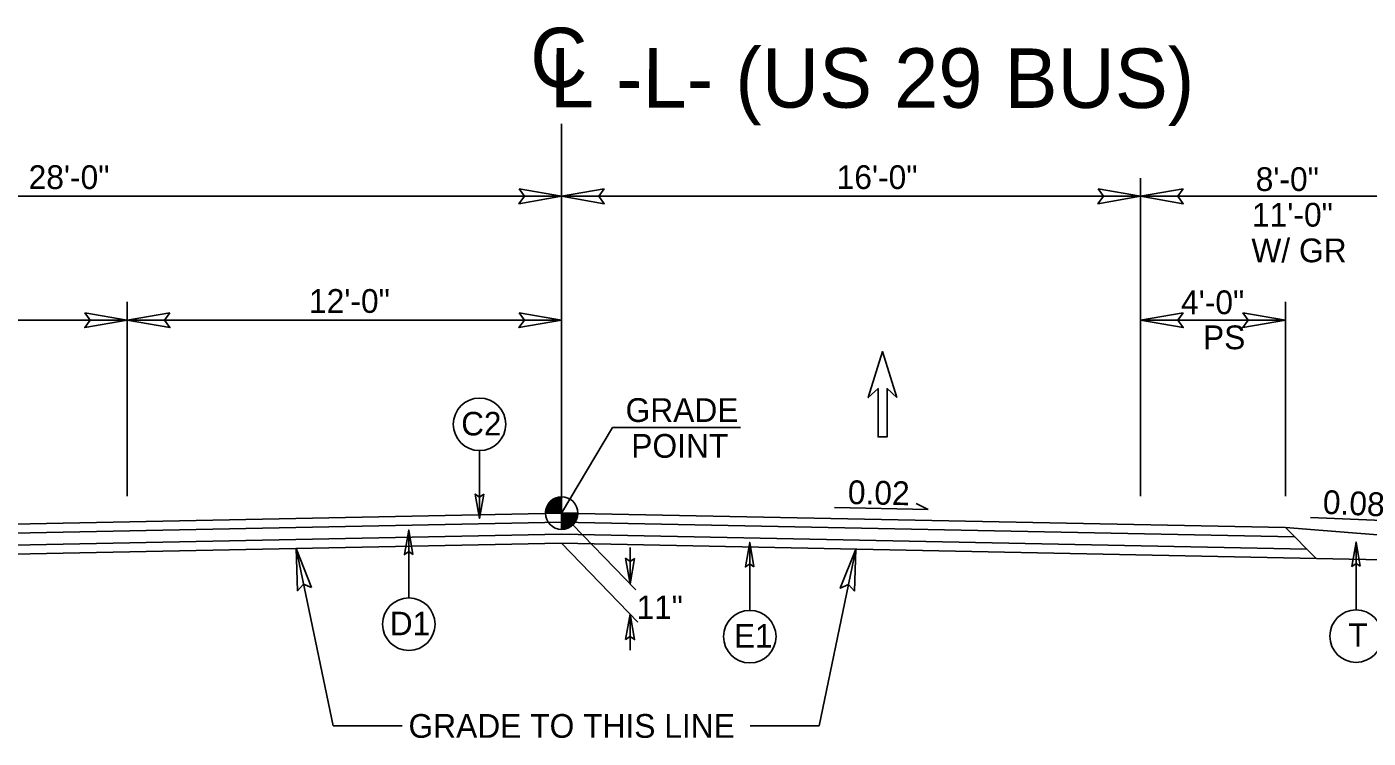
# Model space of a CAD drawing. Extents: x 1901582 to 1902252, y 193723 to 194156.
# Drawn here: x 1902073.81 to 1902110.87, y 194106.96 to 194126.6 of the extents above; entities that cross this region are included whole.
import ezdxf

# ---------------------------------------------------------------- set-up
doc = ezdxf.new("R2010")
doc.units = 0
for name, color, linetype in [('Old_Level_1', 7, 'Continuous'), ('Old_Level_11', 7, 'Continuous'), ('Old_Level_2', 7, 'Continuous'), ('Old_Level_20', 7, 'Continuous'), ('Prop Dimension', 7, 'Continuous'), ('Prop Dimension Text', 7, 'Continuous'), ('Typical Grade Point Symbol CELL', 7, 'Continuous'), ('Typical Pavement Slope Information CELL', 7, 'Continuous'), ('Typical Terminator CELL', 7, 'Continuous'), ('Typical Text Centerline CELL', 7, 'Continuous'), ('Typical Text Grade Point CELL', 7, 'Continuous')]:
    doc.layers.add(name, color=color, linetype=linetype)

# ---------------------------------------------------------------- blocks, each defined once
blk = doc.blocks.new('TERMINATOR')
at = {"layer": 'Typical Terminator CELL'}
blk.add_lwpolyline([(-0.469, 0.081), (0, 0), (-0.471, -0.083), (-0.411, 0)], close=True, dxfattribs=at)

msp = doc.modelspace()

# ---------------------------------------------------------------- linework, layer by layer
at = {"layer": 'Old_Level_1'}
for p, q in [((1902104.586, 194113.636), (1902104.586, 194122.419)), ((1902088.586, 194121.919), (1902060.586, 194121.919)), ((1902104.586, 194121.919), (1902088.586, 194121.919)), ((1902112.586, 194121.919), (1902104.586, 194121.919)), ((1902076.586, 194113.636), (1902076.586, 194119)), ((1902108.586, 194113.636), (1902108.586, 194119)), ((1902076.586, 194118.5), (1902060.586, 194118.5)), ((1902088.586, 194118.5), (1902076.586, 194118.5)), ((1902108.586, 194118.5), (1902104.586, 194118.5)), ((1902088.586, 194113.169), (1902060.586, 194112.609)), ((1902088.586, 194113.169), (1902090.635, 194111.053)), ((1902088.586, 194113.169), (1902108.586, 194112.769)), ((1902088.586, 194112.919), (1902060.586, 194112.359)), ((1902088.586, 194112.919), (1902108.842, 194112.514)), ((1902108.586, 194112.769), (1902109.437, 194111.919)), ((1902108.586, 194112.769), (1902112.586, 194112.449)), ((1902088.586, 194112.336), (1902057.344, 194111.711)), ((1902088.586, 194112.586), (1902057.599, 194111.966)), ((1902088.586, 194112.586), (1902109.182, 194112.174)), ((1902088.586, 194112.336), (1902090.693, 194110.16)), ((1902088.586, 194112.336), (1902115.167, 194111.804)), ((1902081.248, 194112.189), (1902082.271, 194107.298)), ((1902090.477, 194112.216), (1902090.477, 194111.216)), ((1902096.721, 194112.173), (1902095.702, 194107.298)), ((1902090.477, 194110.382), (1902090.477, 194109.382)), ((1902082.271, 194107.298), (1902084.181, 194107.298)), ((1902093.793, 194107.298), (1902095.702, 194107.298))]:
    msp.add_line(p, q, dxfattribs=at)
at = {"layer": 'Old_Level_11'}
for p, q in [((1902088.586, 194113.169), (1902088.586, 194123.919)), ((1902086.319, 194114.895), (1902086.319, 194113.021)), ((1902084.364, 194110.826), (1902084.364, 194112.7)), ((1902093.787, 194110.484), (1902093.787, 194112.358)), ((1902110.54, 194110.497), (1902110.54, 194112.371))]:
    msp.add_line(p, q, dxfattribs=at)
for points in [[(1902086.435, 194113.693), (1902086.319, 194113.021), (1902086.2, 194113.696), (1902086.319, 194113.611)], [(1902084.479, 194112.029), (1902084.364, 194112.7), (1902084.244, 194112.025), (1902084.364, 194112.111)], [(1902093.902, 194111.687), (1902093.787, 194112.358), (1902093.667, 194111.683), (1902093.787, 194111.769)], [(1902110.655, 194111.7), (1902110.54, 194112.371), (1902110.42, 194111.696), (1902110.54, 194111.782)]]:
    msp.add_lwpolyline(points, close=True, dxfattribs=at)
for centre in [(1902086.319, 194115.621), (1902084.364, 194110.101), (1902093.787, 194109.759), (1902110.54, 194109.772)]:
    msp.add_circle(centre, 0.725, dxfattribs=at)
at = {"layer": 'Prop Dimension'}
msp.add_lwpolyline([(1902097.852, 194116.357), (1902097.581, 194116.607), (1902097.581, 194115.274), (1902097.331, 194115.274), (1902097.331, 194116.607), (1902097.06, 194116.357), (1902097.456, 194117.628)], close=True, dxfattribs=at)
msp.add_lwpolyline([(1902097.852, 194116.357), (1902097.581, 194116.607), (1902097.581, 194115.274), (1902097.331, 194115.274), (1902097.331, 194116.607), (1902097.06, 194116.357), (1902097.456, 194117.628)], close=True, dxfattribs=at)
at = {"layer": 'Typical Grade Point Symbol CELL'}
for p, q in [((1902088.586, 194113.169), (1902088.586, 194113.617)), ((1902088.139, 194113.169), (1902088.586, 194113.169)), ((1902088.587, 194112.722), (1902088.586, 194113.169)), ((1902089.034, 194113.169), (1902088.586, 194113.169)), ((1902088.586, 194113.169), (1902088.587, 194112.722))]:
    msp.add_line(p, q, dxfattribs=at)
for points in [[(1902088.171, 194113.334), (1902088.171, 194113.169)], [(1902088.18, 194113.355), (1902088.18, 194113.169)], [(1902088.189, 194113.374), (1902088.189, 194113.169)], [(1902088.197, 194113.39), (1902088.197, 194113.169)], [(1902088.206, 194113.405), (1902088.206, 194113.169)], [(1902088.215, 194113.419), (1902088.215, 194113.169)], [(1902088.224, 194113.432), (1902088.224, 194113.169)], [(1902088.233, 194113.444), (1902088.233, 194113.169)], [(1902088.242, 194113.455), (1902088.242, 194113.169)], [(1902088.251, 194113.466), (1902088.251, 194113.169)], [(1902088.26, 194113.475), (1902088.26, 194113.169)], [(1902088.269, 194113.484), (1902088.269, 194113.169)], [(1902088.278, 194113.493), (1902088.278, 194113.169)], [(1902088.287, 194113.501), (1902088.287, 194113.169)], [(1902088.296, 194113.509), (1902088.296, 194113.169)], [(1902088.305, 194113.517), (1902088.305, 194113.169)], [(1902088.314, 194113.524), (1902088.314, 194113.169)], [(1902088.323, 194113.53), (1902088.323, 194113.169)], [(1902088.332, 194113.537), (1902088.332, 194113.169)], [(1902088.341, 194113.543), (1902088.341, 194113.169)], [(1902088.35, 194113.549), (1902088.35, 194113.169)], [(1902088.359, 194113.554), (1902088.359, 194113.169)], [(1902088.368, 194113.559), (1902088.368, 194113.169)], [(1902088.377, 194113.564), (1902088.377, 194113.169)], [(1902088.385, 194113.569), (1902088.385, 194113.169)], [(1902088.394, 194113.573), (1902088.394, 194113.169)], [(1902088.403, 194113.577), (1902088.403, 194113.169)], [(1902088.412, 194113.581), (1902088.412, 194113.169)], [(1902088.421, 194113.585), (1902088.421, 194113.169)], [(1902088.43, 194113.589), (1902088.43, 194113.169)], [(1902088.439, 194113.592), (1902088.439, 194113.169)], [(1902088.448, 194113.595), (1902088.448, 194113.169)], [(1902088.457, 194113.598), (1902088.457, 194113.169)], [(1902088.466, 194113.6), (1902088.466, 194113.169)], [(1902088.475, 194113.603), (1902088.475, 194113.169)], [(1902088.484, 194113.605), (1902088.484, 194113.169)], [(1902088.493, 194113.607), (1902088.493, 194113.169)], [(1902088.502, 194113.609), (1902088.502, 194113.169)], [(1902088.511, 194113.611), (1902088.511, 194113.169)], [(1902088.52, 194113.612), (1902088.52, 194113.169)], [(1902088.529, 194113.613), (1902088.529, 194113.169)], [(1902088.538, 194113.614), (1902088.538, 194113.169)], [(1902088.547, 194113.615), (1902088.547, 194113.169)], [(1902088.556, 194113.616), (1902088.556, 194113.169)], [(1902088.564, 194113.616), (1902088.564, 194113.169)], [(1902088.573, 194113.617), (1902088.573, 194113.169)], [(1902088.582, 194113.617), (1902088.582, 194113.617), (1902088.582, 194113.169)], [(1902088.144, 194113.233), (1902088.144, 194113.169)], [(1902088.153, 194113.279), (1902088.153, 194113.169)], [(1902088.162, 194113.309), (1902088.162, 194113.169)], [(1902088.593, 194113.169), (1902088.593, 194112.722), (1902088.593, 194112.722)], [(1902088.602, 194113.169), (1902088.602, 194112.722)], [(1902088.611, 194113.169), (1902088.611, 194112.723)], [(1902088.62, 194113.169), (1902088.62, 194112.723)], [(1902088.629, 194113.169), (1902088.629, 194112.724)], [(1902088.638, 194113.169), (1902088.638, 194112.725)], [(1902088.647, 194113.169), (1902088.647, 194112.726)], [(1902088.656, 194113.169), (1902088.656, 194112.728)], [(1902088.665, 194113.169), (1902088.665, 194112.728)], [(1902088.674, 194113.169), (1902088.674, 194112.73)], [(1902088.683, 194113.169), (1902088.683, 194112.732)], [(1902088.692, 194113.169), (1902088.692, 194112.734)], [(1902088.701, 194113.169), (1902088.701, 194112.736)], [(1902088.71, 194113.169), (1902088.71, 194112.739)], [(1902088.719, 194113.169), (1902088.719, 194112.741)], [(1902088.728, 194113.169), (1902088.728, 194112.744)], [(1902088.737, 194113.169), (1902088.737, 194112.747)], [(1902088.746, 194113.169), (1902088.746, 194112.75)], [(1902088.754, 194113.169), (1902088.754, 194112.754)], [(1902088.763, 194113.169), (1902088.763, 194112.758)], [(1902088.772, 194113.169), (1902088.772, 194112.762)], [(1902088.781, 194113.169), (1902088.781, 194112.766)], [(1902088.79, 194113.169), (1902088.79, 194112.77)], [(1902088.799, 194113.169), (1902088.799, 194112.775)], [(1902088.808, 194113.169), (1902088.808, 194112.78)], [(1902088.817, 194113.169), (1902088.817, 194112.785)], [(1902088.826, 194113.169), (1902088.826, 194112.791)], [(1902088.835, 194113.169), (1902088.835, 194112.797)], [(1902088.844, 194113.169), (1902088.844, 194112.803)], [(1902088.853, 194113.169), (1902088.853, 194112.809)], [(1902088.862, 194113.169), (1902088.862, 194112.816)], [(1902088.871, 194113.169), (1902088.871, 194112.823)], [(1902088.88, 194113.169), (1902088.88, 194112.831)], [(1902088.889, 194113.169), (1902088.889, 194112.839)], [(1902088.898, 194113.169), (1902088.898, 194112.847)], [(1902088.907, 194113.169), (1902088.907, 194112.856)], [(1902088.916, 194113.169), (1902088.916, 194112.866)], [(1902088.925, 194113.169), (1902088.925, 194112.876)], [(1902088.934, 194113.169), (1902088.934, 194112.887)], [(1902088.942, 194113.169), (1902088.942, 194112.898)], [(1902088.951, 194113.169), (1902088.951, 194112.91)], [(1902088.96, 194113.169), (1902088.96, 194112.922)], [(1902088.969, 194113.169), (1902088.969, 194112.936)], [(1902088.978, 194113.169), (1902088.978, 194112.952)], [(1902088.987, 194113.169), (1902088.987, 194112.969)], [(1902088.996, 194113.169), (1902088.996, 194112.988)], [(1902089.005, 194113.169), (1902089.005, 194113.009)], [(1902089.014, 194113.169), (1902089.014, 194113.036)], [(1902089.023, 194113.169), (1902089.023, 194113.068)], [(1902089.032, 194113.169), (1902089.032, 194113.12)]]:
    msp.add_lwpolyline(points, dxfattribs=at)
msp.add_circle((1902088.587, 194113.169), 0.448, dxfattribs=at)
for start, end in [(90.0095, 180.0095), (270.0095, 0.0095)]:
    msp.add_arc((1902088.587, 194113.169), 0.448, start, end, dxfattribs=at)
at = {"layer": 'Typical Pavement Slope Information CELL'}
for p, q in [((1902098.716, 194113.27), (1902098.383, 194113.437)), ((1902096.129, 194113.324), (1902098.716, 194113.27)), ((1902109.281, 194113.05), (1902111.867, 194112.935))]:
    msp.add_line(p, q, dxfattribs=at)
at = {"layer": 'Typical Terminator CELL'}
for points in [[(1902087.415, 194122.121), (1902088.586, 194121.919), (1902087.408, 194121.711), (1902087.558, 194121.919)], [(1902089.758, 194122.121), (1902088.586, 194121.919), (1902089.765, 194121.711), (1902089.615, 194121.919)], [(1902103.415, 194122.121), (1902104.586, 194121.919), (1902103.408, 194121.711), (1902103.558, 194121.919)], [(1902105.758, 194122.121), (1902104.586, 194121.919), (1902105.765, 194121.711), (1902105.615, 194121.919)], [(1902075.415, 194118.702), (1902076.586, 194118.5), (1902075.408, 194118.292), (1902075.558, 194118.5)], [(1902077.758, 194118.702), (1902076.586, 194118.5), (1902077.765, 194118.292), (1902077.615, 194118.5)], [(1902087.415, 194118.702), (1902088.586, 194118.5), (1902087.408, 194118.292), (1902087.558, 194118.5)], [(1902105.758, 194118.702), (1902104.586, 194118.5), (1902105.765, 194118.292), (1902105.615, 194118.5)], [(1902107.415, 194118.702), (1902108.586, 194118.5), (1902107.408, 194118.292), (1902107.558, 194118.5)], [(1902081.674, 194111.113), (1902081.248, 194112.189), (1902081.285, 194111.026), (1902081.453, 194111.21)], [(1902096.68, 194111.017), (1902096.721, 194112.173), (1902096.288, 194111.093), (1902096.517, 194111.194)]]:
    msp.add_lwpolyline(points, close=True, dxfattribs=at)
at = {"layer": 'Typical Text Grade Point CELL'}
for p, q in [((1902088.586, 194113.169), (1902089.99, 194115.53)), ((1902089.99, 194115.53), (1902093.528, 194115.53))]:
    msp.add_line(p, q, dxfattribs=at)

# ---------------------------------------------------------------- block references
at = {"layer": 'Old_Level_1', "xscale": 1.5, "yscale": 1.5}
for p, rotation in [((1902090.477, 194111.216), -90), ((1902090.477, 194110.382), 90)]:
    msp.add_blockref('TERMINATOR', p, dxfattribs=dict(at, rotation=rotation))

# ---------------------------------------------------------------- texts
at = {"layer": 'Old_Level_1'}
for s, p in [('28\'-0"', (1902073.859, 194122.117)), ('16\'-0"', (1902096.187, 194122.117)), ('8\'-0"', (1902107.766, 194122.063)), ('11\'-0"', (1902107.664, 194121.079)), ('W/ GR', (1902107.647, 194120.095)), ('12\'-0"', (1902081.607, 194118.698)), ('4\'-0"', (1902105.703, 194118.662)), ('GRADE TO THIS LINE', (1902084.356, 194106.965))]:
    msp.add_text(s, height=0.656, dxfattribs=at).set_placement(p)
at = {"layer": 'Old_Level_2'}
for s, rotation, p in [('0.02', 358.8084, (1902096.491, 194113.421)), ('0.08', 357.4644, (1902109.61, 194113.152))]:
    msp.add_text(s, height=0.656, rotation=rotation, dxfattribs=at).set_placement(p)
at = {"layer": 'Old_Level_20'}
for s, height, p in [('C2', 0.6491, (1902085.813, 194115.314)), ('11"', 0.6491, (1902090.663, 194110.245)), ('D1', 0.6491, (1902083.842, 194109.797)), ('E1', 0.6491, (1902093.353, 194109.455)), ('T', 0.649, (1902110.329, 194109.479))]:
    msp.add_text(s, height=height, dxfattribs=at).set_placement(p)
at = {"layer": 'Prop Dimension Text'}
msp.add_text('PS', height=0.656, dxfattribs=at).set_placement((1902106.309, 194117.694))
at = {"layer": 'Typical Text Centerline CELL'}
msp.add_text('C', height=1.64, dxfattribs=at).set_placement((1902087.718, 194124.931))
msp.add_text('L -L- (US 29 BUS)', height=1.64109, rotation=359.9469, dxfattribs=at).set_placement((1902088.264, 194124.371))
at = {"layer": 'Typical Text Grade Point CELL'}
for s, p in [('GRADE', (1902090.354, 194115.686)), ('POINT', (1902090.511, 194114.697))]:
    msp.add_text(s, height=0.656, dxfattribs=at).set_placement(p)

doc.saveas('drawing.dxf')
